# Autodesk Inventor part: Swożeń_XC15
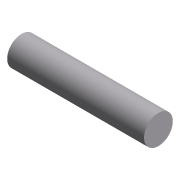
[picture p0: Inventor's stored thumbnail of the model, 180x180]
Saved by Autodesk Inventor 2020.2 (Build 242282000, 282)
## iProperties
Created: 2000-05
Part Number: Swożeń_XC15
Document SubType Name: Modeling
Designer: F.Stasiak
Stock Number: Swożeń_XC15
Density: 1 g/cm^3
Material: Default
Appearance: Aluminium (matowe)
Manager: www.cadconsulting.pl
Company: Fabian Stasiak CAD Consulting
Control State: 0
Master: False
Checked Out: False
Shininess: 0.0
Density: 0.0
Volumn: 0.0
Area: 0.0
PropertySet Name: Model Information
Author: F.Stasiak
Subject: Zbiór ćwiczeń. Autodesk Inventor 2020. Kurs podstawowy
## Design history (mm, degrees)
node "Base1"
node "Bryła1"
node "Korpusy bryłowe"
node "Korpusy powierzchniowe"
